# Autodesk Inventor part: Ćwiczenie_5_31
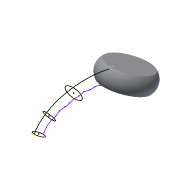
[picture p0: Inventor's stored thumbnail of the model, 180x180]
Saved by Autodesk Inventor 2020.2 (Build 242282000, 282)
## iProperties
Created: 2005-03
Part Number: Ćwiczenie_5_31
Document SubType Name: Modeling
Designer: F.Stasiak
Manufacturer: Standard
Standards Organization: Custom
Density: 1 g/cm^3
Material: Ogólny
Appearance: Domyślna
Manager: www.cadconsulting.pl
Company: Fabian Stasiak CAD Consulting
Author: F.Stasiak
Subject: Zbiór ćwiczeń. Autodesk Inventor 2020. Kurs podstawowy
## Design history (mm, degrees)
sketch "Szkic2"
  geometry: L1 (-125, 100)-(125, 100); L2 (125, 100)-(125, 0); L3 (125, 0)-(-125, 0); L4 (-125, 0)-(-125, 100); 5 further points
  constraints: 8 end point, 2 midpoint, 2 parallel, 1 coincident, 1 horizontal, 1 perpendicular, 4 other
  dimensions: "d0" = 250 distance of L2.end L3.end; "d1" = 100 distance of L3.end L1.start
sketch "Szkic3"
  geometry: L1 (124.721, 76.924)-(189.98, 51.602); L2 (189.98, 51.602)-(170.084, 0.327); L3 (170.084, 0.327)-(102.086, 26.712); A1 r 40 centre (139.851, 39.896) between (124.721, 76.924) and (102.086, 26.712); 1 further point
  constraints: 6 end point, 2 point on circle, 1 centre point, 1 parallel, 1 perpendicular
  dimensions: "d5" = 70 distance of L1.start L1.end; "d6" = 55 distance between parallel lines of L3 L1; "d7" = 30 distance from line of point (125, 50) L3; "d17" = 40 radius of A1; "d18" = 120 diameter of point (125, 50) L2; "d19" = 85 diameter of A1.centre L2
revolve "Obrót1" sketch "Szkic3" stored, may be unused: angle "d8" = 90 deg
node "Płaszczyzna konstrukcyjna1"
node "Płaszczyzna konstrukcyjna2"
node "Płaszczyzna konstrukcyjna3"
node "Płaszczyzna konstrukcyjna4"
sketch "Szkic4"
  geometry: C1 r 17.5 at (0, 0) reference; 1 further point
  constraints: 1 centre point, 1 coincident, 1 other
sketch "Szkic5"
  geometry: 2 further points; 1 other entity
  constraints: 1 coincident, 2 other
sketch "Szkic6"
  geometry: 2 further points; 1 other entity
  constraints: 1 coincident, 2 other
sketch "Szkic7"
  geometry: 2 further points; 1 other entity
  constraints: 1 coincident, 2 other
node "Punkt konstrukcyjny1"
node "Punkt konstrukcyjny2"
node "Punkt konstrukcyjny3"
node "Punkt konstrukcyjny4"
sketch "Szkic8"
  geometry: 4 further points
  constraints: 4 other
node "Punkt konstrukcyjny5"
node "Punkt konstrukcyjny6"
node "Punkt konstrukcyjny7"
node "Punkt konstrukcyjny8"
sketch "Szkic9"
  geometry: L1 (-124.067, -36.595)-(-94.775, 20.652); A1 r 68.009 centre (-48.878, -38.951) between (-90.371, 14.933) and (-116.853, -36.821); 13 further points
  constraints: 2 end point, 2 midpoint, 1 centre point, 1 point on circle, 15 other
node "Bryła1"
node "Korpusy bryłowe"
node "Korpusy powierzchniowe"
